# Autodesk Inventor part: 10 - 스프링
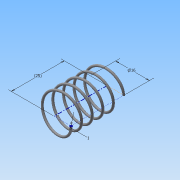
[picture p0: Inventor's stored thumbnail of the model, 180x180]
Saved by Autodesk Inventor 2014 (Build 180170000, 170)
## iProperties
Created: 2015-06
Part Number: 10 - 스프링
Material: 강철, 연강
Document SubType Name: Modeling
Designer: Administrator
Density: 7.86 g/cm^3
Appearance: 강철
Mass: 1.53479 g
Surface Area: 7.89194 cm^2
Volume: 0.195266 cm^3
Author: Administrator
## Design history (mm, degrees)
sketch "스케치1"
  geometry: L1 (0, 0)-(8, 0); L2 (8, 0)-(8, 21.5); L3 (8, 21.5)-(0, 21.5); L4 (0, 21.5)-(0, 0); C1 r 0.5 at (8, 0)
  constraints: 8 end point, 2 parallel, 1 centre point, 1 coincident, 1 horizontal, 1 perpendicular
  dimensions: "d0" = 21.5 distance between parallel lines of L1 L3 (derived); "d1" = 16 diameter of L2 L4; "d2" = 1 diameter of C1
feature "코일1" sketch "스케치1" pitch "d3" = 10; turns "d5" = 5; dims "d4" = 21.5 (= d0), "d6" = 0, angle "d7" = 90 deg, angle "d8" = 90 deg, "d9" = 0, "d10" = 0
node "작업 평면1"
sketch "스케치2"
  geometry: L1 (-8.5, 0)-(-7.5, 0) reference; 1 further point
  constraints: 1 horizontal alignment
extrude "돌출1" cut sketch "스케치2" distance "d12" = 10; taper "d13" = 0 deg
node "작업 평면2"
sketch "스케치3"
  geometry: L1 (-7.5, 0)-(-8.5, 0) reference; 1 further point
  constraints: 1 horizontal alignment
extrude "돌출2" cut sketch "스케치3" stored distance "d15" = 10; taper "d16" = 0 deg
node "솔리드1"
node "절단 모서리 투영1"
node "절단 모서리 투영2"
other parameters: "d11" = 0, "d14" = 21.5 (= d0)
